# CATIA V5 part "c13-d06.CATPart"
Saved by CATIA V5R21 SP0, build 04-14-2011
Part number: Part1
Bounding box of the stored display mesh (mm): x -40 to 40, y -65 to 65, z 0 to 15
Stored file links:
  D:\CATIA V5R21 E-RESOURCES\CATIA-V5R21\catia-v5r21-prt\c13-catia-v5r20-prt\c13-catia-v5r20-figr-13-19\cat_v5r21_c13-d06.CATPart
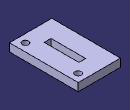
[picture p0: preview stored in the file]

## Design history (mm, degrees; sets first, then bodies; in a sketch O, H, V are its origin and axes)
Body1 (main body)
  Sketch1 on xy-plane, origin (0, 0, 0), H (1, 0, 0), V (0, 1, 0)
    line L1 (40, 65) -> (40, -65)
    line L2 (40, -65) -> (-40, -65)
    line L3 (-40, -65) -> (-40, 65)
    line L4 (-40, 65) -> (40, 65)
    length L1 = 130
    length L2 = 80
    vertical: L1 V, L3 V
    horizontal: L2 H, L4 H
    equidistance: L1 L3 O, L2 L4 O
  Pad1: profile Sketch1, direction (0, 0, 1), length 15
  Sketch2 on face of Pad1, origin (0, 0, 15), H (1, 0, 0), V (0, 1, 0)
    line L1 (6.4019, 32.7538) -> (6.4019, -32.7538)
    line L2 (6.4019, -32.7538) -> (-6.4019, -32.7538)
    line L3 (-6.4019, -32.7538) -> (-6.4019, 32.7538)
    line L4 (-6.4019, 32.7538) -> (6.4019, 32.7538)
    vertical: L1 V, L3 V
    horizontal: L2 H, L4 H
    equidistance: L1 L3 O, L2 L4 O
  Pocket1: profile Sketch2, direction (0, 0, -1), through (limit type 3)
  Sketch3 on face of Pad1, origin (30.5043, -33.5377, 15), H (1, 0, 0), V (0, 1, 0)
    point P1 (-5.5043, -16.4623)
    reference projected line E1 (9.4957, -31.4623) -> (9.4957, 98.5377) from edge [face of Pad1 | face of Pad1]
    reference projected line E2 (-70.5043, -31.4623) -> (9.4957, -31.4623) from edge [face of Pad1 | face of Pad1]
    distance P1 E1 = 15
    distance P1 E2 = 15
  Hole1: placed by Sketch3, at (25, -50, 15) direction (0, 0, -1), diameter 12, through (limit type 3)
  Mirror1: of Hole1, about zx-plane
